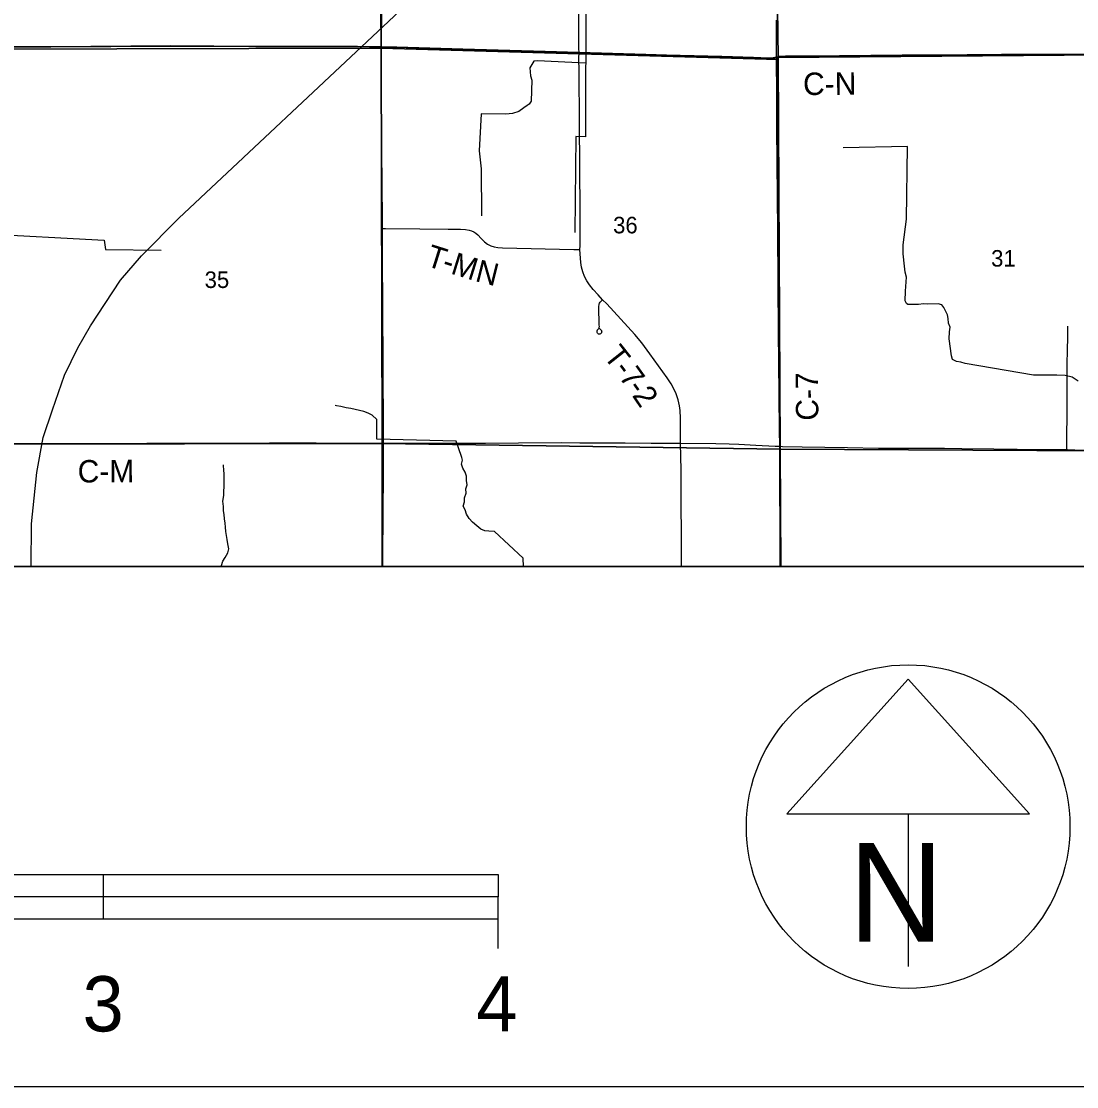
# Model space of a CAD drawing. Extents: x 0 to 34, y 0 to 22.
# Drawn here: x 27.01 to 29.684, y 14 to 16.699 of the extents above; entities that cross this region are included whole.
import ezdxf

# ---------------------------------------------------------------- set-up
doc = ezdxf.new("R2010")
doc.units = 0
for name, color, linetype in [('GM_X_County_Road', 7, 'Continuous'), ('GM_X_County_Road_Text', 7, 'Continuous'), ('GM_X_Minor_River', 7, 'Continuous'), ('GM_X_Rail_Line', 7, 'Continuous'), ('GM_X_Section', 7, 'Continuous'), ('GM_X_Section_Text', 7, 'Continuous'), ('GM_X_Township_Road', 7, 'Continuous'), ('GM_X_Township_Road_Text', 7, 'Continuous'), ('GM_X_Township_Text', 7, 'Continuous'), ('SC_Scratch1', 7, 'Continuous'), ('SH_Data', 7, 'Continuous'), ('SH_Masking', 7, 'Continuous'), ('SH_Text', 7, 'Continuous')]:
    doc.layers.add(name, color=color, linetype=linetype)

msp = doc.modelspace()

# ---------------------------------------------------------------- linework, layer by layer
at = {"layer": 'GM_X_County_Road'}
for points in [[(28.9238, 16.608), (28.9236, 16.6123), (28.9231, 16.6838), (28.9231, 16.7024)], [(26.9163, 16.6335), (26.9633, 16.6336), (27.0846, 16.6341), (27.3892, 16.6364), (27.4981, 16.6359), (27.6038, 16.635), (27.7748, 16.6349), (27.8618, 16.6351), (27.9219, 16.634)], [(27.9219, 16.634), (27.9613, 16.6333), (28.1291, 16.6281), (28.3373, 16.6219), (28.4231, 16.6192)], [(28.4231, 16.6192), (28.4803, 16.6174), (28.5922, 16.6144), (28.645, 16.6129), (28.7849, 16.6094), (28.8657, 16.6068), (28.9029, 16.6055), (28.9153, 16.6059), (28.9191, 16.6066), (28.9238, 16.608)], [(28.9238, 16.608), (28.9258, 16.6086), (28.9279, 16.6091), (28.9301, 16.6094), (28.9321, 16.6096), (28.9337, 16.6096), (28.9467, 16.6099), (28.9871, 16.6102), (29.0835, 16.611), (29.2421, 16.6126), (29.3136, 16.6131), (29.4069, 16.6137), (29.4939, 16.6141), (29.5686, 16.6147), (29.7054, 16.6149), (29.7956, 16.6154), (29.8484, 16.6158), (29.9075, 16.616), (30.0319, 16.6162), (30.0694, 16.6162)], [(28.9321, 15.6224), (28.931, 15.6638), (28.9297, 15.838), (28.9288, 15.9095), (28.9275, 16.037), (28.9269, 16.1676), (28.9249, 16.4288), (28.9243, 16.5096), (28.9238, 16.608)], [(26.924, 15.6292), (26.9736, 15.6293), (27.0358, 15.6295), (27.0731, 15.6295), (27.1632, 15.6296), (27.2627, 15.6299), (27.328, 15.6301), (27.5799, 15.6306), (27.6389, 15.6309), (27.7571, 15.6311), (27.8751, 15.6306), (27.9275, 15.6305)], [(27.9275, 15.6305), (27.987, 15.6304), (28.1114, 15.6302), (28.186, 15.6306), (28.2699, 15.6308), (28.3787, 15.6318), (28.4254, 15.6314), (28.4564, 15.6314), (28.5403, 15.6312), (28.6056, 15.6307), (28.6806, 15.6302)], [(28.6806, 15.6302), (28.7694, 15.6295), (28.8031, 15.629), (28.8278, 15.6281), (28.8713, 15.6255), (28.9199, 15.6229), (28.9321, 15.6224)], [(28.6831, 15.3175), (28.683, 15.338), (28.6817, 15.537), (28.682, 15.5433), (28.6817, 15.5493), (28.6817, 15.5617), (28.6806, 15.6302)], [(28.9321, 15.6224), (28.9389, 15.6223), (28.9886, 15.6212), (29.1037, 15.6192), (29.1815, 15.618), (29.2592, 15.6175), (29.3121, 15.6176), (29.3495, 15.6176), (29.393, 15.6169), (29.4739, 15.616), (29.533, 15.6152), (29.6263, 15.6142), (29.656, 15.6143), (29.6591, 15.6142)], [(29.6591, 15.6142), (29.6607, 15.6141), (29.679, 15.6136), (29.7471, 15.6123), (29.8186, 15.6118), (29.8746, 15.6113), (29.9243, 15.6114), (30.0114, 15.6107), (30.0611, 15.6111), (30.0703, 15.6113)]]:
    msp.add_lwpolyline(points, dxfattribs=at)
at = {"layer": 'GM_X_Minor_River'}
for points in [[(28.4399, 16.7728), (28.4392, 16.4063), (28.4153, 16.4069), (28.4126, 16.1644)], [(28.4396, 16.5933), (28.3175, 16.5994), (28.3087, 16.5984), (28.2986, 16.5815), (28.2999, 16.561), (28.3032, 16.5499), (28.3019, 16.4972), (28.2968, 16.4896), (28.2919, 16.4855), (28.2835, 16.4803), (28.2708, 16.4706), (28.2541, 16.4658), (28.2378, 16.4641), (28.1749, 16.4651), (28.1704, 16.371), (28.1748, 16.3254), (28.1761, 16.2063)], [(29.6882, 15.7874), (29.6728, 15.7978), (29.6546, 15.8021), (29.6334, 15.8027), (29.5747, 15.803), (29.4019, 15.8321), (29.3906, 15.8356), (29.3792, 15.8369), (29.3698, 15.8423), (29.3665, 15.8514), (29.3606, 15.8944), (29.3616, 15.9126), (29.3637, 15.9239), (29.3596, 15.9346), (29.3583, 15.9464), (29.3565, 15.9551), (29.3473, 15.9738), (29.3428, 15.9807), (29.333, 15.983), (29.3053, 15.9822), (29.2958, 15.9834), (29.2833, 15.982), (29.2738, 15.9818), (29.2602, 15.9819), (29.256, 15.9816), (29.2527, 15.9846), (29.2493, 15.9911), (29.2504, 16.0158), (29.2522, 16.0393), (29.2531, 16.0506), (29.2491, 16.0632), (29.2478, 16.0791), (29.244, 16.1099), (29.2447, 16.1327), (29.2527, 16.1982), (29.2551, 16.3821), (29.0921, 16.3789)], [(26.906, 16.1617), (27.2201, 16.1448), (27.2236, 16.1212), (27.3646, 16.1191)], [(27.9106, 15.6906), (27.8993, 15.7013), (27.8884, 15.7063), (27.8778, 15.711), (27.8665, 15.713), (27.8555, 15.7158), (27.8449, 15.7178), (27.8332, 15.7198), (27.8192, 15.723), (27.8082, 15.7246), (27.8052, 15.7258)], [(28.1249, 15.5966), (28.112, 15.6354), (27.9108, 15.6405), (27.9106, 15.6906)], [(27.5159, 15.3175), (27.5171, 15.3207), (27.5206, 15.3313), (27.5268, 15.3411), (27.533, 15.3524), (27.5354, 15.363), (27.5329, 15.3752), (27.5311, 15.3866), (27.5297, 15.3965), (27.5283, 15.4067), (27.5273, 15.4178), (27.5263, 15.4273), (27.5249, 15.4383), (27.5235, 15.4493), (27.5224, 15.4592), (27.5218, 15.4702), (27.5204, 15.4831), (27.5229, 15.4979), (27.523, 15.5085), (27.5239, 15.5199), (27.5236, 15.5305), (27.5237, 15.5411), (27.5235, 15.5514), (27.5229, 15.5628), (27.5226, 15.5726), (27.5222, 15.5757)], [(28.2088, 15.4068), (28.1948, 15.4077), (28.1845, 15.4086), (28.1743, 15.4128), (28.1638, 15.4205), (28.1533, 15.4298), (28.1447, 15.4397), (28.1376, 15.4508), (28.1343, 15.4611), (28.1299, 15.471), (28.1327, 15.4819), (28.1328, 15.4918), (28.1367, 15.5039), (28.1364, 15.5149), (28.14, 15.5251), (28.1382, 15.5354), (28.1376, 15.5468), (28.1346, 15.5567), (28.1287, 15.5666), (28.125, 15.5773), (28.1278, 15.5871), (28.1257, 15.5941), (28.1249, 15.5966)], [(28.2826, 15.3175), (28.2819, 15.3389), (28.2088, 15.4068)]]:
    msp.add_lwpolyline(points, dxfattribs=at)
at = {"layer": 'GM_X_Rail_Line'}
msp.add_lwpolyline([(27.0345, 15.3175), (27.0356, 15.4259), (27.0494, 15.5562), (27.0656, 15.6449), (27.0886, 15.7152), (27.1197, 15.8028), (27.1531, 15.872), (27.1854, 15.9273), (27.2223, 15.9838), (27.2614, 16.0437), (27.3144, 16.1048), (27.4089, 16.2005), (27.94, 16.6983), (28.7611, 17.4753), (29.4921, 18.1638), (30.1262, 18.7537), (30.3167, 18.9329)], dxfattribs=at)
at = {"layer": 'GM_X_Section'}
for points in [[(26.9089, 17.6314), (27.9132, 17.6317), (27.9213, 16.6311), (26.9154, 16.6284)], [(27.9132, 17.6317), (28.9139, 17.6013), (28.9274, 16.6074), (28.9273, 16.6021), (27.9213, 16.6311)], [(28.914, 17.6074), (30.0593, 17.6044), (30.0675, 16.617), (28.9274, 16.6074), (28.9139, 17.6013)], [(26.9154, 16.6284), (27.9213, 16.6311), (27.924, 15.6297), (26.9227, 15.6274)], [(27.9213, 16.6311), (28.9273, 16.6021), (28.9324, 15.6152), (27.924, 15.6297)], [(28.9274, 16.6074), (30.0675, 16.617), (30.0715, 15.6092), (28.9324, 15.6152), (28.9273, 16.6021)]]:
    msp.add_lwpolyline(points, close=True, dxfattribs=at)
for points in [[(26.9227, 15.3175), (26.9227, 15.6274), (27.924, 15.6297), (27.924, 15.3175)], [(27.924, 15.3175), (27.924, 15.6297), (28.9324, 15.6152), (28.9345, 15.3175)], [(28.9345, 15.3175), (28.9324, 15.6152), (30.0715, 15.6092), (30.0727, 15.3175)]]:
    msp.add_lwpolyline(points, dxfattribs=at)
at = {"layer": 'GM_X_Township_Road'}
for points in [[(28.4231, 16.6192), (28.4229, 16.6313), (28.4227, 16.681), (28.4217, 16.7868), (28.4209, 16.8708), (28.4205, 16.9205), (28.4195, 17.0667), (28.4192, 17.1009), (28.4187, 17.1538), (28.4171, 17.359), (28.4168, 17.4026), (28.4164, 17.4865), (28.4158, 17.5363), (28.4152, 17.6079), (28.4152, 17.6177)], [(27.9219, 16.634), (27.9221, 16.6407), (27.9232, 16.6997), (27.9233, 16.7526), (27.9229, 16.8365), (27.9222, 16.8955), (27.921, 16.9515), (27.9199, 17.026), (27.9194, 17.054), (27.9193, 17.1193), (27.9191, 17.1337)], [(26.9163, 16.6335), (26.9633, 16.6336), (27.0846, 16.6341), (27.3892, 16.6364), (27.4981, 16.6359), (27.6038, 16.635), (27.7748, 16.6349), (27.8618, 16.6351), (27.9219, 16.634)], [(27.9251, 16.1745), (27.9251, 16.1799), (27.9249, 16.2047), (27.9244, 16.2792), (27.9229, 16.4783), (27.922, 16.5839), (27.9219, 16.634)], [(27.9219, 16.634), (27.9613, 16.6333), (28.1291, 16.6281), (28.3373, 16.6219), (28.4231, 16.6192)], [(28.4254, 16.1214), (28.4256, 16.1307), (28.4261, 16.2176), (28.4241, 16.4416), (28.4231, 16.5722), (28.4227, 16.6064), (28.4231, 16.6192)], [(28.4231, 16.6192), (28.4803, 16.6174), (28.5922, 16.6144), (28.645, 16.6129), (28.7849, 16.6094), (28.8657, 16.6068), (28.9029, 16.6055), (28.9153, 16.6059), (28.9191, 16.6066), (28.9238, 16.608)], [(27.9275, 15.6305), (27.9275, 15.6573), (27.9274, 15.7102), (27.9271, 15.7755), (27.9266, 15.8719), (27.9261, 15.931), (27.9252, 16.1456), (27.9251, 16.1745)], [(27.9251, 16.1745), (27.9329, 16.1744), (28.0201, 16.1735), (28.0917, 16.1728), (28.1229, 16.1725), (28.1354, 16.1718), (28.1447, 16.1702), (28.1508, 16.1683), (28.1565, 16.1657), (28.162, 16.1624), (28.1669, 16.1584), (28.1755, 16.1492), (28.1839, 16.1402), (28.1911, 16.1346), (28.1992, 16.1302), (28.208, 16.1275), (28.2171, 16.1259), (28.2294, 16.125), (28.4097, 16.1213), (28.4254, 16.1214)], [(28.4829, 15.9938), (28.4719, 16.006), (28.4592, 16.0197), (28.4493, 16.0316), (28.4425, 16.0418), (28.4369, 16.0527), (28.4325, 16.0642), (28.4294, 16.0761), (28.4278, 16.0882), (28.4254, 16.1214)], [(28.4744, 15.9221), (28.4777, 15.9184), (28.4786, 15.9174), (28.4794, 15.9164), (28.4799, 15.9156), (28.4804, 15.9143), (28.4805, 15.913), (28.4804, 15.9115), (28.48, 15.9101), (28.4794, 15.9089), (28.4786, 15.9079), (28.4775, 15.9071), (28.4762, 15.9065), (28.4748, 15.9063), (28.4741, 15.9064), (28.4731, 15.9066), (28.4723, 15.9068), (28.4716, 15.9073), (28.4705, 15.9081), (28.4696, 15.9092), (28.4691, 15.9105), (28.4687, 15.9118), (28.4687, 15.9132), (28.4689, 15.9145), (28.4693, 15.9156), (28.4697, 15.9164), (28.4702, 15.9172), (28.4709, 15.918), (28.4715, 15.9188), (28.4727, 15.92), (28.4734, 15.921), (28.4739, 15.9219), (28.4742, 15.923), (28.4743, 15.9239), (28.4746, 15.9258), (28.4745, 15.9289), (28.4735, 15.9761), (28.474, 15.9822), (28.475, 15.9848), (28.4767, 15.9873), (28.4829, 15.9938)], [(28.6806, 15.6302), (28.68, 15.6669), (28.6799, 15.694), (28.6791, 15.7127), (28.6774, 15.7251), (28.674, 15.7404), (28.669, 15.7552), (28.6628, 15.7695), (28.6568, 15.7805), (28.6461, 15.7958), (28.6028, 15.8565), (28.5826, 15.8842), (28.5646, 15.9056), (28.4934, 15.9834), (28.4829, 15.9938)], [(29.6591, 15.6142), (29.6591, 15.6153), (29.6592, 15.6206), (29.6594, 15.6453), (29.6602, 15.7042), (29.6603, 15.7786), (29.6601, 15.8313), (29.6605, 15.8654), (29.6614, 15.8995), (29.6619, 15.915), (29.662, 15.9269)], [(27.9259, 15.3175), (27.9262, 15.3619), (27.9266, 15.4334), (27.9274, 15.5733), (27.9275, 15.62), (27.9275, 15.6305)]]:
    msp.add_lwpolyline(points, dxfattribs=at)
at = {"layer": 'GM_X_Township_Text'}
for points in [[(28.9329, 15.3175), (28.9318, 15.6229), (28.9308, 15.6644), (28.9294, 15.8385), (28.9286, 15.91), (28.9273, 16.0375), (28.9267, 16.1681), (28.9247, 16.4293), (28.924, 16.5102), (28.9235, 16.6085), (28.9189, 16.6071), (28.9151, 16.6064), (28.9027, 16.6061), (28.8654, 16.6073), (28.7846, 16.6099), (28.6448, 16.6135), (28.592, 16.6149), (28.4801, 16.618), (28.4229, 16.6198), (28.3371, 16.6225), (28.1289, 16.6287), (27.9611, 16.6338), (27.9217, 16.6346), (27.8616, 16.6356), (27.7745, 16.6355), (27.6035, 16.6355), (27.4978, 16.6364), (27.389, 16.637), (27.0843, 16.6346), (26.9631, 16.6342)], [(29.7052, 16.6155), (29.5683, 16.6152), (29.4937, 16.6147), (29.4066, 16.6142), (29.3134, 16.6136), (29.2418, 16.6131), (29.0832, 16.6116), (28.9868, 16.6108), (28.9464, 16.6104), (28.9334, 16.6102), (28.9319, 16.6101), (28.9299, 16.61), (28.9277, 16.6097), (28.9256, 16.6091), (28.9235, 16.6085), (28.924, 16.5102), (28.9247, 16.4293), (28.9267, 16.1681), (28.9273, 16.0375), (28.9286, 15.91), (28.9294, 15.8385), (28.9308, 15.6644), (28.9318, 15.6229), (28.9329, 15.3175)]]:
    msp.add_lwpolyline(points, dxfattribs=at)
at = {"layer": 'SC_Scratch1'}
msp.add_lwpolyline([(23.5167, 20.6789), (23.5167, 15.3175), (30.3167, 15.3175), (30.3167, 20.8109), (30.0181, 20.8047), (28.8862, 20.7941), (27.8891, 20.7835), (26.8843, 20.7634), (25.88, 20.7414), (25.1253, 20.7174), (23.8668, 20.6853)], close=True, dxfattribs=at)
at = {"layer": 'SH_Data'}
for p, q in [((26.2178, 14.5375), (27.2178, 14.5375)), ((27.2178, 14.4812), (27.2178, 14.5375)), ((27.2178, 14.5375), (28.2178, 14.5375)), ((28.2178, 14.5375), (28.2178, 14.4812)), ((27.2178, 14.4812), (26.2178, 14.4812)), ((27.2178, 14.425), (27.2178, 14.4812)), ((28.2178, 14.4812), (27.2178, 14.4812)), ((28.2178, 14.35), (28.2178, 14.4812)), ((26.2178, 14.425), (27.2178, 14.425)), ((27.2178, 14.425), (28.2178, 14.425))]:
    msp.add_line(p, q, dxfattribs=at)
for points in [[(23.4167, 21), (30.4167, 21), (30.4167, 14), (23.4167, 14)], [(23.5167, 20.9), (30.3167, 20.9), (30.3167, 15.3175), (23.5167, 15.3175)]]:
    msp.add_lwpolyline(points, close=True, dxfattribs=at)
at = {"layer": 'SH_Masking'}
msp.add_circle((29.2571, 14.6588), 0.41, dxfattribs=at)
at = {"layer": 'SH_Text'}
for p, q in [((29.2571, 15.0325), (28.9495, 14.6913)), ((29.5647, 14.6913), (29.2571, 15.0325)), ((28.9495, 14.6913), (29.5647, 14.6913)), ((29.2571, 14.6913), (29.2571, 14.3045))]:
    msp.add_line(p, q, dxfattribs=at)
msp.add_circle((29.2571, 14.6588), 0.41, dxfattribs=at)

# ---------------------------------------------------------------- texts
at = {"layer": 'GM_X_County_Road_Text'}
for s, rotation, p in [('C-N', 0.3977, (28.9909, 16.5122)), ('C-7', 90.4581, (29.0297, 15.6876)), ('C-M', 0.3636, (27.1528, 15.5306))]:
    msp.add_text(s, height=0.05682, rotation=rotation, dxfattribs=at).set_placement(p)
at = {"layer": 'GM_X_Section_Text'}
for s, p in [('36', (28.5094, 16.1619)), ('31', (29.4673, 16.0777)), ('35', (27.4744, 16.0235))]:
    msp.add_text(s, height=0.04186, rotation=0, dxfattribs=at).set_placement(p)
at = {"layer": 'GM_X_Township_Road_Text'}
for s, rotation, p in [('T', 342.5734, (28.0325, 16.0803)), ('-', 342.5936, (28.0731, 16.0676)), ('M', 342.7092, (28.0955, 16.0606)), ('N', 345.8475, (28.1576, 16.0413)), ('T', 308.2997, (28.4831, 15.8502)), ('-', 306.1439, (28.509, 15.8173)), ('7', 305.522, (28.5227, 15.7986)), ('2', 303.895, (28.5563, 15.7514)), ('-', 305.4115, (28.543, 15.7701))]:
    msp.add_text(s, height=0.0568, rotation=rotation, dxfattribs=at).set_placement(p)
at = {"layer": 'SH_Text'}
for s, height, p in [('N', 0.25, (29.1058, 14.3674)), ('3', 0.14, (27.1651, 14.14)), ('4', 0.14, (28.1627, 14.14))]:
    msp.add_text(s, height=height, dxfattribs=at).set_placement(p)

doc.saveas('drawing.dxf')
